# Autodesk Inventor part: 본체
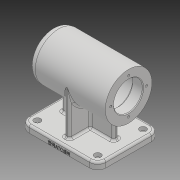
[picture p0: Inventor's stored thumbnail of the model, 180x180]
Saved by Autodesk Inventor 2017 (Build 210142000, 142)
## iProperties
Part Number: 본체
Material: 일반
Document SubType Name: Modeling
Designer: 222
Density: 1 g/cm^3
Appearance: 기본값
Mass: 380.103 g
Surface Area: 757.984 cm^2
Volume: 380.103 cm^3
Author: 222
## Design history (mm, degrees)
sketch "스케치1"
  geometry: L1 (56, 0)-(-56, 0); L2 (-56, 0)-(-56, 34); L3 (-56, 34)-(56, 34); L4 (56, 34)-(56, 0); 2 further points
  constraints: 8 end point, 2 parallel, 1 coincident, 1 horizontal, 1 midpoint, 1 perpendicular
  dimensions: "d0" = 112 distance of L2.end L3.end; "d1" = 68 diameter of L3 L1
revolve "회전1" sketch "스케치1" stored, may be unused: angle "d2" = 90 deg
sketch "스케치2"
  geometry: L1 (-56, -34)-(-56, 34) reference; L2 (-56, 34)-(56, 34) reference; L3 (56, 34)-(56, -34) reference; L4 (56, -34)-(-56, -34) reference; L5 (56, -64)-(-56, -64); L6 (-56, -64)-(-56, -74); L7 (-56, -74)-(56, -74); L8 (56, -74)-(56, -64); 1 further point
  constraints: 8 end point, 2 parallel, 1 horizontal, 1 perpendicular, 1 vertical alignment
  dimensions: "d3" = 74 distance from line of L7 point (0, 0); "d4" = 10 distance of L5.end L6.end; "d5" = 112 distance of L6.end L7.end
extrude "돌출1" join sketch "스케치2" stored distance "d6" = 90; taper "d7" = 0 deg
sketch "스케치3"
  geometry: L1 (-56, -34)-(-56, 34) reference; L2 (-56, 34)-(56, 34) reference; L3 (56, 34)-(56, -34) reference; L4 (56, -34)-(-56, -34) reference; L5 (56, -64)-(56, -74) reference; L6 (56, -74)-(-56, -74) reference; L7 (-56, -74)-(-56, -64) reference; L8 (-56, -64)-(56, -64) reference; L9 (38, -14)-(-38, -14); L10 (-38, -14)-(-38, -64); L11 (-38, -64)-(38, -64); L12 (38, -64)-(38, -14); 1 further point
  constraints: 8 end point, 2 parallel, 1 horizontal, 1 horizontal alignment, 1 perpendicular
  dimensions: "d8" = 18 distance from line of L6.end L10; "d9" = 18 distance from line of L5.end L12; "d10" = 50 distance of L9.end L10.end
extrude "돌출2" join sketch "스케치3" stored distance "d11" = 8; taper "d12" = 0 deg
sketch "스케치4"
  geometry: L1 (-45, -74)-(-45, -64) reference; L2 (-45, -64)-(-4, -64) reference; L3 (-4, -64)-(-4, -33.764) reference; L4 (4, -33.764)-(4, -64) reference; L5 (4, -64)-(45, -64) reference; L6 (45, -64)-(45, -74) reference; L7 (45, -74)-(-45, -74) reference; L8 (-34, 0)-(34, 0); L9 (34, 0)-(34, -64); L10 (34, -64)-(-34, -64); L11 (-34, -64)-(-34, 0); A1 r 34 centre (0, 0) between (4, -33.764) and (-4, -33.764) reference; 2 further points
  constraints: 8 end point, 2 coincident, 2 parallel, 1 horizontal, 1 horizontal alignment, 1 midpoint, 1 perpendicular
  dimensions: "d13" = 68 distance of L8.start L8.end
extrude "돌출3" join sketch "스케치4" stored distance "d15" = 8; taper "d16" = 0 deg
sketch "스케치5"
  geometry: L1 (-56, -34)-(-56, 34) reference; L2 (-56, 34)-(56, 34) reference; L3 (56, 34)-(56, -34) reference; L4 (56, -34)-(38, -34) reference; L5 (38, -34)-(38, -64) reference; L6 (38, -64)-(56, -64) reference; L7 (56, -64)-(56, -74) reference; L8 (56, -74)-(-56, -74) reference; L9 (-56, -74)-(-56, -64) reference; L10 (-56, -64)-(-38, -64) reference; L11 (-38, -64)-(-38, -34) reference; L12 (-38, -34)-(-56, -34) reference; L13 (-56, 0)-(-41, 0); L14 (-41, 0)-(-41, 21); L15 (-41, 21)-(-56, 21); L16 (-56, 21)-(-56, 0); L17 (-41, 0)-(13, 0); L18 (13, 0)-(13, 24); L19 (13, 24)-(-41, 24); L20 (-41, 24)-(-41, 0); L21 (13, 0)-(25, 0); L22 (25, 0)-(25, 21); L23 (25, 21)-(13, 21); L24 (13, 21)-(13, 0); L25 (25, 0)-(43, 0); L26 (43, 0)-(43, 17.5); L27 (43, 17.5)-(25, 17.5); L28 (25, 17.5)-(25, 0); L29 (43, 0)-(47, 0); L30 (47, 0)-(47, 16); L31 (47, 16)-(43, 16); L32 (43, 16)-(43, 0); L33 (47, 0)-(50, 0); L34 (50, 0)-(50, 10.5); L35 (50, 10.5)-(47, 10.5); L36 (47, 10.5)-(47, 0); 1 further point
  constraints: 48 end point, 12 parallel, 6 horizontal, 6 perpendicular, 1 midpoint
  dimensions: "d17" = 3 distance of L34.end L35.end; "d18" = 4 distance of L30.end L31.end; "d19" = 18 distance of L26.end L27.end; "d20" = 12 distance of L22.end L23.end; "d21" = 54 distance of L18.end L19.end; "d22" = 15 distance of L14.end L15.end; "d23" = 42 diameter of L15 L13; "d24" = 48 diameter of L19 L17; "d25" = 42 diameter of L23 L21; "d26" = 35 diameter of L27 L25; "d27" = 32 diameter of L31 L29; "d28" = 21 diameter of L35 L33
revolve "회전2" sketch "스케치5" stored, may be unused: angle "d29" = 90 deg
fillet "모깎기1" dims "d30" = 3, "d31" = 0.3
chamfer "모따기1" distance "d32" = 1; stored, may be unused: second distance "d33" = 2, angle "d34" = 45 deg
sketch "스케치6"
  geometry: 2 further points
  constraints: 1 horizontal alignment
  dimensions: "d35" = 26 distance of point (0, 0) point (-26, 0)
hole "구멍1" sketch "스케치6" at (-26, 0) diameter "d36" = 3.242; stored, may be unused: countersink angle "d40" = 90 deg, drill point angle "d42" = 118 deg; dims "d37" = 8, "d38" = 4, "d39" = 2, "d41" = 11
fillet "모깎기2" dims "d46" = 12
sketch "스케치7"
  geometry: L1 (100, 78)-(100, 12) reference; L2 (88, 0)-(0, 0) reference; L3 (-12, 12)-(-12, 78) reference; L4 (0, 90)-(88, 90) reference; L5 (40, 11)-(40, 41) reference; L6 (40, 41)-(6, 41) reference; L7 (6, 41)-(6, 49) reference; L8 (6, 49)-(40, 49) reference; L9 (40, 49)-(40, 79) reference; L10 (40, 79)-(48, 79) reference; L11 (48, 79)-(48, 49) reference; L12 (48, 49)-(82, 49) reference; L13 (82, 49)-(82, 41) reference; L14 (82, 41)-(48, 41) reference; L15 (48, 41)-(48, 11) reference; L16 (48, 11)-(40, 11) reference; A1 r 12 centre (88, 78) between (100, 78) and (88, 90) reference; A2 r 12 centre (88, 12) between (88, 0) and (100, 12) reference; A3 r 12 centre (0, 12) between (-12, 12) and (0, 0) reference; A4 r 12 centre (0, 78) between (0, 90) and (-12, 78) reference; 5 further points
  constraints: 4 coincident
hole "구멍2" sketch "스케치7" at (0, 78), (0, 12), (88, 78), (88, 12) diameter "d47" = 5.5; stored, may be unused: countersink angle "d51" = 90 deg, drill point angle "d53" = 118 deg; dims "d48" = 8, "d49" = 9.5, "d50" = 5.4, "d52" = 11
fillet "모깎기3" dims "d54" = 10
fillet "모깎기4" dims "d55" = 3
fillet "모깎기5" dims "d56" = 3
fillet "모깎기6" dims "d57" = 3
fillet "모깎기7" dims "d58" = 3
node "작업 평면1"
sketch "스케치8"
  geometry: L1 (56, -74)-(56, -67) reference; L2 (56, -74)-(44, -74) reference; 2 further points
  constraints: 1 other
  dimensions: "d60" = 56 distance from line of point (0, -71) L1; "d61" = 3 distance from line of point (0, -71) L2
feature "엠보싱1" sketch "스케치8" dims "d0" = 112, "d1" = 68, "d8" = 18, "d9" = 18, "d10" = 50, "d62" = 0.5, "d63" = 0
node "솔리드1"
pattern_circular "원형 패턴1" dims angle "d44" = 360 deg
node "절단 모서리 투영1"
node "절단 모서리 투영2"
node "절단 모서리 투영3"
node "절단 모서리 투영4"
node "절단 모서리 투영5"
